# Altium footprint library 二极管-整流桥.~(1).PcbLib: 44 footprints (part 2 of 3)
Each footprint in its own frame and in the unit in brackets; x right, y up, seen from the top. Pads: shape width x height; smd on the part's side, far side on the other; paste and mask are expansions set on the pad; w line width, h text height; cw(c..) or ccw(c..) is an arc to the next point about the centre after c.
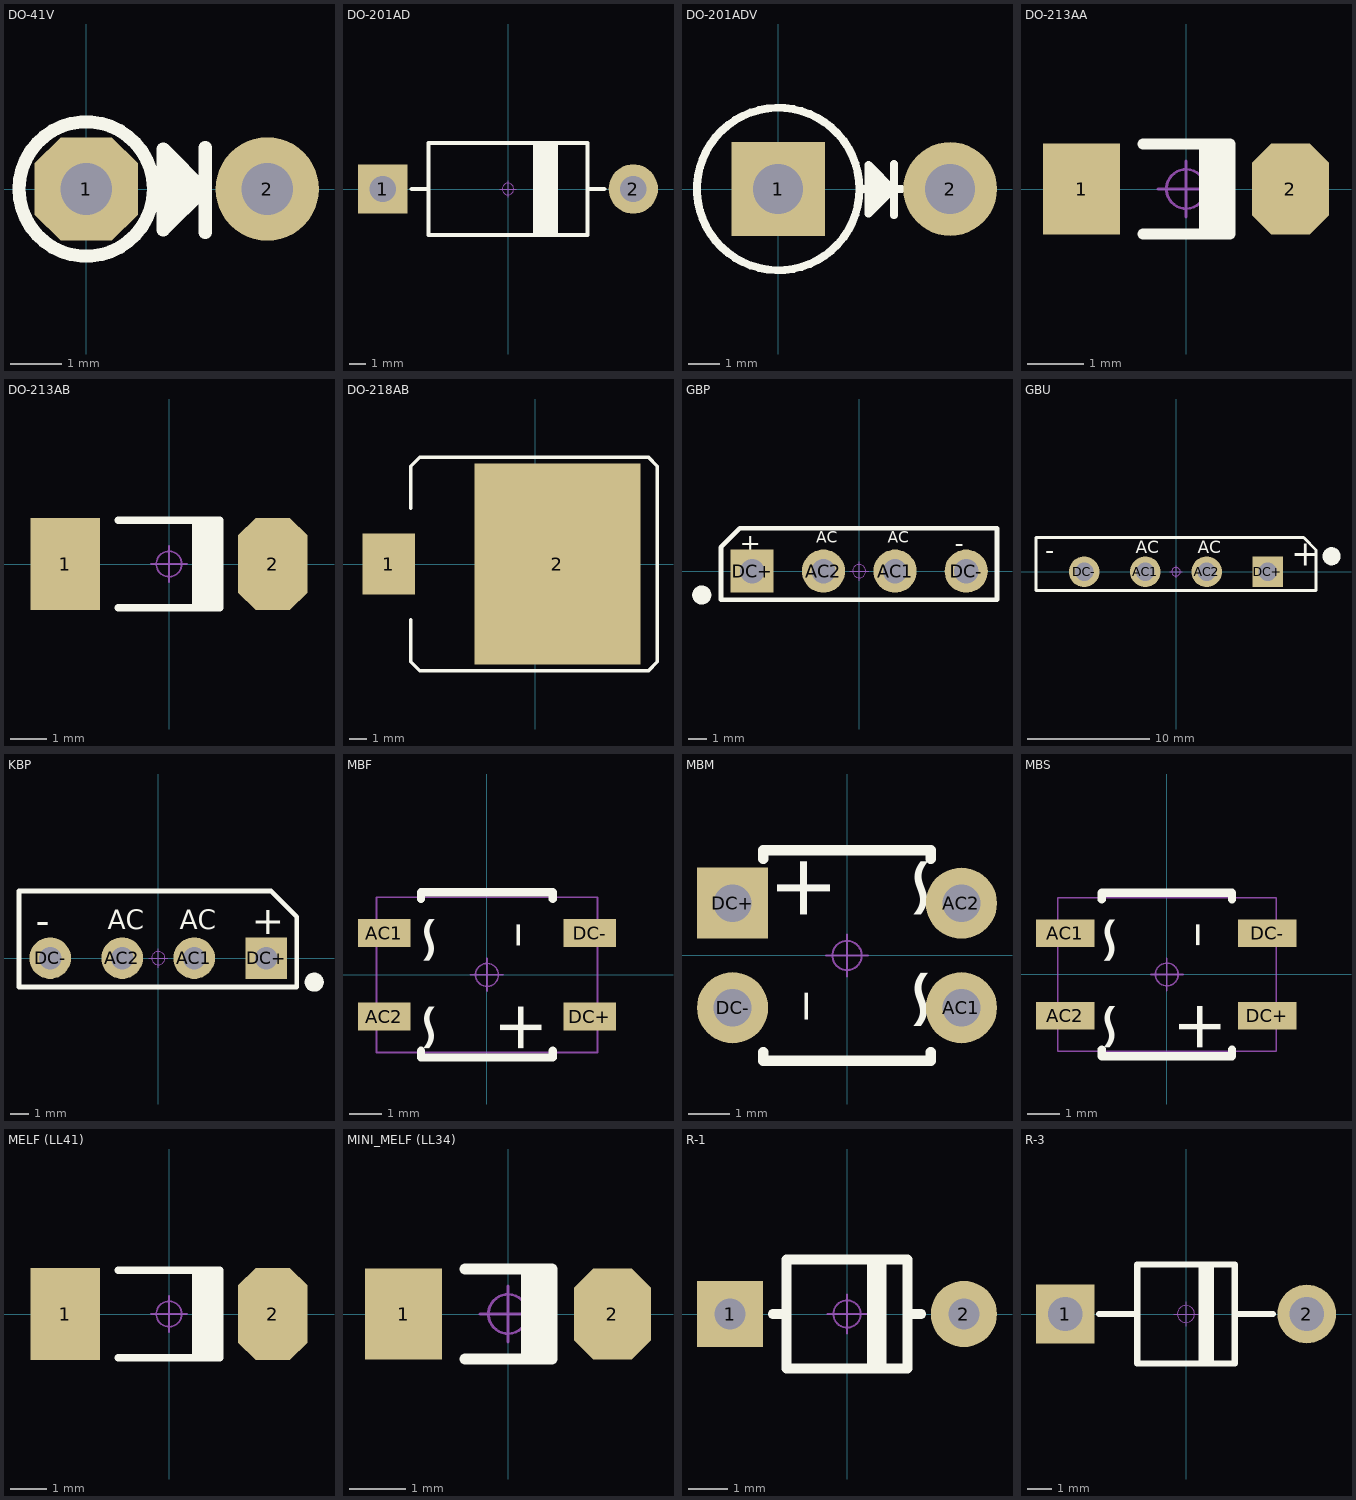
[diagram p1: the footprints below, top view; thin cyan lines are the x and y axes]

## DO-41V [mm] "2.6*3.5mm(直径，脚距）"
height 2.4
pads (2):
  oct 2x2 hole 1: 1(0,0)
  round 2 hole 1: 2(3.5,0)
Top Overlay:
  circle w0.254: c0,0 r1.3
  lines w0.254: 1.651,0.559 1.676,-0.432 2.159,0 1.905,0.254 1.905,0 1.905,-0.254 ; 2.261,-0.02 1.488,-0.792 1.488,0.775 2.301,-0.038 ; 2.301,-0.841 2.301,0.805
3D body: height 6.9, standoff -3.5, extent -1.301,-1.301 3.9,1.301

## DO-201AD [mm] "5.2*15.2mm(直径，脚距）"
pads (2):
  rect 3x3 hole 1.6: 1(-7.6,0)
  round 3 hole 1.6: 2(7.6,0)
Top Overlay:
  rectangle: 1.524,-2.794 3.048,2.794
  lines w0.254: -5.842,0 -4.826,0 ; 4.826,0 5.842,0 ; -4.826,-2.794 -4.826,2.794 4.826,2.794 4.826,-2.794 -4.826,-2.794
Mechanical 15:
  circle w0.05: c0,0 r0.35
  lines w0.05: -0.5,0 0.5,0 ; 0,-0.5 0,0.5
3D body: height 5.25, standoff -3.46, extent -8.25,-2.601 8.25,2.601

## DO-201ADV [mm] "5.2*5.5mm(直径，脚距）"
pads (2):
  rect 3x3 hole 1.6: 1(0,0)
  round 3 hole 1.6: 2(5.5,0)
Top Overlay:
  circle w0.254: c0,0 r2.6
  lines w0.254: 2.616,0 3.698,0 ; 3.048,0.559 3.073,-0.432 3.556,0 ; 3.302,-0.254 3.302,0 3.302,0.254 3.556,0 ; 3.658,-0.02 2.885,-0.792 2.885,0.775 3.698,-0.038 ; 3.698,-0.841 3.698,0.805 ; 3.937,0 3.556,0
3D body: height 12, standoff -3.46, extent -2.601,-2.601 6.15,2.601

## DO-213AA [mm] "1.5*3.5mm(直径，脚距）"
pads (2):
  rect 1.37x1.62 smd: 1(-1.855,0)
  oct 1.37x1.62 smd: 2(1.855,0)
Top Overlay:
  rectangle: 0.227,-0.8 0.777,0.8
  lines w0.2: -0.762,-0.8 0.777,-0.8 0.777,0.8 -0.762,0.8
Mechanical 15:
  circle w0.05: c0,0 r0.35
  lines w0.05: -0.5,0 0.5,0 ; 0,-0.5 0,0.5
3D body: height 1.53, standoff 0.03, extent -1.75,-0.751 1.75,0.751

## DO-213AB [mm] "2.5*5.6mm(直径，脚距）"
height 2.54
pads (2):
  rect 1.9x2.54 smd: 1(-2.85,0)
  oct 1.9x2.54 smd: 2(2.85,0)
Top Overlay:
  rectangle: 0.635,-1.2 0.85,1.2
  rectangle: 0.85,-1.2 1.4,1.2
  lines w0.2: -1.4,-1.2 1.4,-1.2 1.4,1.2 -1.4,1.2
Mechanical 15:
  circle w0.05: c0,0 r0.35
  lines w0.05: -0.5,0 0.5,0 ; 0,-0.5 0,0.5
3D body: height 2.55, standoff 0.05, extent -2.53,-1.251 2.53,1.251

## DO-218AB [mm] "长：13.7mm，宽：10.5mm，厚：5mm"
height 2.54
pads (2):
  rect 3x3.5 smd: 1(-8.382,0)
  rect 9.5x11.5 smd: 2(1.27,0)
Top Overlay:
  lines w0.2: -7.112,-3.175 -7.112,-5.588 -6.604,-6.096 6.477,-6.096 6.985,-5.588 6.985,5.588 6.477,6.096 -6.604,6.096 -7.112,5.588 -7.112,3.175
Mechanical 15:
  circle w0.05: c0,0 r0.35
  lines w0.05: -0.5,0 0.5,0 ; 0,-0.5 0,0.5
3D body: height 5.02, standoff 0.02, extent -9.35,-5.25 6.85,5.25

## GBP [mm] "14.2*2.9*10.5mm(长宽高)"
pads (4):
  round 2.3 hole 1.3: AC1(1.91,0) AC2(-1.9,0) DC-(5.7,0)
  rect 2.3x2.3 hole 1.3: DC+(-5.7,0)
Top Overlay:
  circle w0.508: c-8.382,-1.27 r0.254
  lines w0.254: -7.36,-1.524 -7.36,1.276 -6.35,2.286 7.34,2.286 7.34,-1.524 -7.36,-1.524
  text "AC" at 1.524,1.524 h0.6
  text "+" at -6.35,1.016 h1
  text "-" at 5.08,1.016 h1
  text "AC" at -2.286,1.524 h0.6
Mechanical 15:
  circle w0.05: c0,0 r0.35
  lines w0.05: -0.5,0 0.5,0 ; 0,-0.5 0,0.5
3D body: height 12.8, standoff -3.6, extent -7.1,-1 7.1,1.9

## GBU [mm] "整流桥，脚距：5mm/200mil"
pads (4):
  round 2.5 hole 1.5: AC1(-2.5,0) AC2(2.5,0) DC-(-7.5,0)
  rect 2.5x2.5 hole 1.5: DC+(7.5,0)
Top Overlay:
  circle w0.762: c12.7,1.27 r0.359
  lines w0.254: -11.43,-1.524 11.43,-1.524 11.43,1.778 10.414,2.794 -8.422,2.794 -11.43,2.794 -11.43,-1.524
  text "AC" at 1.778,1.524 h1.02
  text "AC" at -3.302,1.524 h1.02
  text "+" at 9.398,0.508 h2.03
  text "-" at -10.668,1.016 h1.52
Mechanical 15:
  circle w0.05: c0,0 r0.35
  lines w0.05: -0.5,0 0.5,0 ; 0,-0.5 0,0.5
3D body: height 20.8, standoff -4, extent -11,-1.15 11,2.35

## KBP [mm] "14.7*4.8*12.2mm(长宽高)"
pads (4):
  round 2.2 hole 1.2: AC1(1.9,0) AC2(-1.91,0) DC-(-5.72,0)
  rect 2.2x2.2 hole 1.2: DC+(5.71,0)
Top Overlay:
  circle w0.508: c8.25,-1.27 r0.254
  lines w0.254: -7.37,-1.524 -7.37,3.55 5.97,3.55 7.33,2.19 7.33,-1.524 -7.37,-1.524
  text "+" at 4.948,1.27 h1.5
  text "-" at -6.482,1.27 h1.5
  text "AC" at -2.672,1.524 h1.02
  text "AC" at 1.138,1.524 h1.02
Mechanical 15:
  circle w0.05: c0,0 r0.35
  lines w0.05: -0.5,0 0.5,0 ; 0,-0.5 0,0.5
3D body: height 11.7, standoff -3.1, extent -7.35,-1.25 7.35,3.55

## MBF [mm] "4.7*7*1.5mm(长宽高)"
height 12.3
pads (4):
  rect 1.6x0.85 smd: AC1(-3.127,1.27) AC2(-3.127,-1.27) DC+(3.127,-1.27) DC-(3.127,1.27)
Top Overlay:
  lines w0.254: -2.007,-2.311 -2.007,-2.515 2.007,-2.515 2.007,-2.311 ; -2.007,2.311 -2.007,2.515 2.007,2.515 2.007,2.311
  text "+" at 2.159,-0.762 h2.54
  text "-" at 2.159,1.651 h3.05
  text "~" at -0.635,-0.762 h2.54
  text "~" at -0.635,1.905 h2.54
Mechanical 13:
  lines w0.05: -3.363,-2.363 -3.363,2.362 3.363,2.362 3.363,-2.363 -3.363,-2.363
Mechanical 15:
  circle w0.05: c0,0 r0.35
  lines w0.05: -0.5,0 0.5,0 ; 0,-0.5 0,0.5
3D body: height 1.6, standoff -0.03, extent -3.5,-2.35 3.5,2.35

## MBM [mm] "4.8*5.2*2.5mm(长宽高)"
pads (4):
  round 1.7 hole 0.9: AC1(2.737,-1.25) AC2(2.737,1.25) DC-(-2.737,-1.25)
  rect 1.7x1.7 hole 0.9: DC+(-2.737,1.25)
Top Overlay:
  lines w0.254: -2.007,-2.311 -2.007,-2.515 2.007,-2.515 2.007,-2.311 ; -2.007,2.311 -2.007,2.515 2.007,2.515 2.007,2.311
  text "~" at 0.635,-1.905 h2.54
  text "~" at 0.635,0.762 h2.54
  text "-" at -2.159,-1.651 h3.05
  text "+" at -2.159,0.762 h2.54
Mechanical 15:
  circle w0.05: c0,0 r0.35
  lines w0.05: -0.5,0 0.5,0 ; 0,-0.5 0,0.5
3D body: height 2.6, standoff -3.11, extent -3.154,-2.4 3.094,2.4

## MBS [mm] "4.1*6.8*2.5mm(长宽高)"
height 12.3
pads (4):
  rect 1.8x0.85 smd: AC1(-3.127,1.27) AC2(-3.127,-1.27) DC+(3.096,-1.27) DC-(3.096,1.27)
Top Overlay:
  lines w0.254: -2.007,-2.311 -2.007,-2.515 2.007,-2.515 2.007,-2.311 ; -2.007,2.311 -2.007,2.515 2.007,2.515 2.007,2.311
  text "+" at 2.159,-0.762 h2.54
  text "-" at 2.159,1.651 h3.05
  text "~" at -0.635,-0.762 h2.54
  text "~" at -0.635,1.905 h2.54
Mechanical 13:
  lines w0.05: -3.363,-2.363 3.363,-2.363 3.363,2.362 -3.363,2.362 -3.363,-2.363
Mechanical 15:
  circle w0.05: c0,0 r0.35
  lines w0.05: -0.5,0 0.5,0 ; 0,-0.5 0,0.5
3D body: height 2.6, standoff -0.03, extent -3.4,-2.4 3.4,2.4

## MELF (LL41) [mm] "2.4*5.3mm(直径，脚距）"
height 2.54
pads (2):
  rect 1.9x2.54 smd: 1(-2.85,0)
  oct 1.9x2.54 smd: 2(2.85,0)
Top Overlay:
  rectangle: 0.635,-1.2 0.85,1.2
  rectangle: 0.85,-1.2 1.4,1.2
  lines w0.2: -1.4,-1.2 1.4,-1.2 1.4,1.2 -1.4,1.2
Mechanical 15:
  circle w0.05: c0,0 r0.35
  lines w0.05: -0.5,0 0.5,0 ; 0,-0.5 0,0.5
3D body: height 2.4, standoff 0, extent -2.651,-1.2 2.651,1.2

## MINI_MELF (LL34) [mm] "1.5*3.4mm(直径，脚距）"
pads (2):
  rect 1.37x1.62 smd: 1(-1.855,0)
  oct 1.37x1.62 smd: 2(1.855,0)
Top Overlay:
  rectangle: 0.227,-0.8 0.777,0.8
  lines w0.2: -0.762,-0.8 0.777,-0.8 0.777,0.8 -0.762,0.8
Mechanical 15:
  circle w0.05: c0,0 r0.35
  lines w0.05: -0.5,0 0.5,0 ; 0,-0.5 0,0.5
3D body: height 1.5, standoff 0, extent -1.701,-0.75 1.701,0.75

## R-1 [mm] "2.5*6mm(直径，脚距）"
pads (2):
  rect 1.7x1.7 hole 0.8: 1(-3,0)
  round 1.7 hole 0.8: 2(3,0)
Top Overlay:
  rectangle: 0.508,-1.397 1.016,1.397
  lines w0.254: -1.905,0 -1.55,0 ; 1.55,0 1.905,0 ; -1.55,-1.397 -1.55,1.397 1.55,1.397 1.55,-1.397 -1.55,-1.397
Mechanical 15:
  circle w0.05: c0,0 r0.35
  lines w0.05: -0.5,0 0.5,0 ; 0,-0.5 0,0.5
3D body: height 2.55, standoff -3.45, extent -3.3,-1.251 3.3,1.251

## R-3 [mm] "3.9*9.9mm(直径，脚距）"
pads (2):
  rect 2.4x2.4 hole 1.4: 1(-4.95,0)
  round 2.4 hole 1.4: 2(4.95,0)
Top Overlay:
  rectangle: 0.508,-2.032 1.143,2.032
  lines w0.254: -3.556,0 -2,0 ; 2.032,0 3.556,0 ; -2,-2.032 -2,2.032 2,2.032 2,-2.032 -2,-2.032
Mechanical 15:
  circle w0.05: c0,0 r0.35
  lines w0.05: -0.5,0 0.5,0 ; 0,-0.5 0,0.5
3D body: height 3.95, standoff -3.45, extent -5.5,-1.951 5.5,1.951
